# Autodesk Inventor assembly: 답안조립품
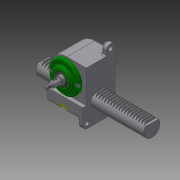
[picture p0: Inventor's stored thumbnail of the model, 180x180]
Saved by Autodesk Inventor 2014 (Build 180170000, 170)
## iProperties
Created: 2019-06
Part Number: 답안조립품
Document SubType Name: Assembly
Designer: net
Author: net
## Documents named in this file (10)
- C:\Users\net\Desktop\390604V1032\답안조립품.iam
- C:\Users\net\Desktop\390604V1032\본체.ipt
- C:\Users\net\Desktop\390604V1032\뒤커버.ipt
- C:\Users\net\Desktop\390604V1032\베어링 6003.ipt
- C:\Users\net\Desktop\390604V1032\피니언.ipt
- C:\Users\net\Desktop\390604V1032\앞커버.ipt
- C:\Users\net\Desktop\390604V1032\오일 실 17 30 5.ipt
- C:\Users\net\Desktop\390604V1032\래크.ipt
- C:\Users\net\Desktop\390604V1032\누름쇠.ipt
- C:\Users\net\Desktop\390604V1032\볼트 M4.ipt
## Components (1 placed, 1 different names)
1. 피니언:1 — 각도:1
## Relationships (1: Angle 1)
- 각도:1 [Angle]: 피니언:1
